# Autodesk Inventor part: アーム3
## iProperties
Created: 2008-02
Part Number: アーム3
Document SubType Name: Modeling
Designer: y-shimazaki
Density: 1 g/cm^3
Author: y-shimazaki
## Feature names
1. 押し出し1 [Extrusion]
2. 押し出し2 [Extrusion]
3. 押し出し3 [Extrusion]
4. 押し出し4 [Extrusion]
5. 押し出し5 [Extrusion]
6. ミラー1 [Mirror]
